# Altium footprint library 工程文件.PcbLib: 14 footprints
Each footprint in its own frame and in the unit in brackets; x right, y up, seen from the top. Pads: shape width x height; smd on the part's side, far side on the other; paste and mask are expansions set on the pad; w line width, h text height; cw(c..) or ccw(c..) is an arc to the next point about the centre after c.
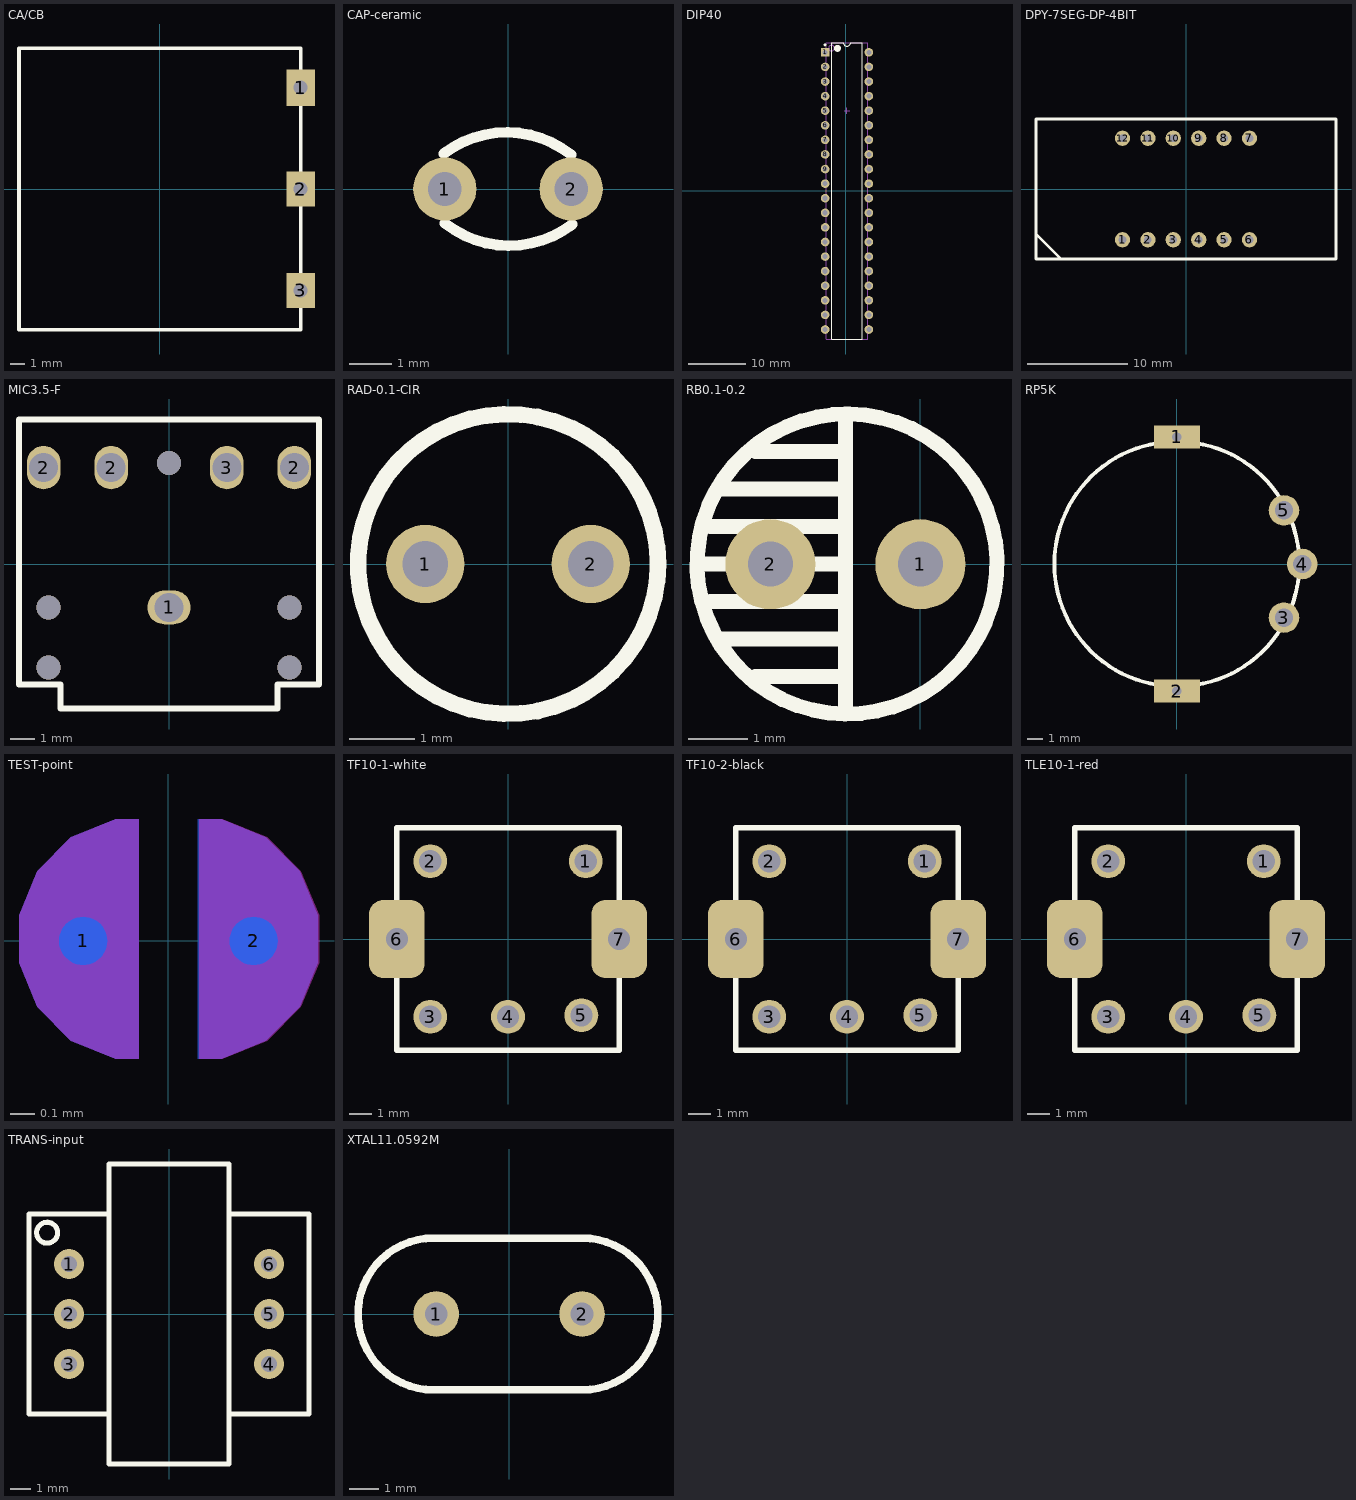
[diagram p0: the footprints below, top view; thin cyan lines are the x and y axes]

## CA/CB [mm]
pads (3):
  rect 2x2.6 hole 1 square: 1(10,7.2)
  rect 2x2.5 hole 1 square: 2(10,0) 3(10,-7.2)
Top Overlay:
  lines w0.254: -10,-10 10,-10 10,10 -10,10 -10,-10

## CAP-ceramic [mm]
pads (2):
  round 1.5 hole 0.8: 1(-1.5,0) 2(1.5,0)
Top Overlay:
  lines w0.254: -1.524,0.838 cw(c-0.029,-1.108) 1.499,0.813 ; -1.499,-0.813 ccw(c0.029,1.108) 1.524,-0.838

## DIP40 [mm]
pads (40):
  rect 1.5x1.5 hole 0.9: 1(-3.556,24.13)
  round 1.5 hole 0.9: 2(-3.556,21.59) 3(-3.556,19.05) 4(-3.556,16.51) 5(-3.556,13.97) 6(-3.556,11.43) 7(-3.556,8.89) 8(-3.556,6.35) 9(-3.556,3.81) 10(-3.556,1.27) 11(-3.556,-1.27) 12(-3.556,-3.81) 13(-3.556,-6.35) 14(-3.556,-8.89) 15(-3.556,-11.43) 16(-3.556,-13.97) 17(-3.556,-16.51) 18(-3.556,-19.05) 19(-3.556,-21.59) 20(-3.556,-24.13) 21(4.064,-24.13) 22(4.064,-21.59) 23(4.064,-19.05) 24(4.064,-16.51) 25(4.064,-13.97) 26(4.064,-11.43) 27(4.064,-8.89) 28(4.064,-6.35) 29(4.064,-3.81) 30(4.064,-1.27) 32(4.064,3.81) 33(4.064,6.35) 34(4.064,8.89) 35(4.064,11.43) 36(4.064,13.97) 37(4.064,16.51) 38(4.064,19.05) 39(4.064,21.59) 40(4.064,24.13)
  round 1.524 hole 0.762: 31(4.064,1.27)
Top Overlay:
  circle w0.6: c-1.396,24.82 r0.3
  circle w0.25: c-3.556,25.43 r0.125
  lines w0.2: -2.396,-25.781 -2.396,25.82 -0.381,25.82 ccw(c0.254,25.82) 0.889,25.82 2.904,25.82 2.904,-25.781 -2.396,-25.781
Mechanical 13:
  circle w0.1: c-2.446,24.87 r0.5
  lines w0.1: -3.346,-25.781 -3.346,25.77 3.854,25.77 3.854,-25.781 -3.346,-25.781
Mechanical 15:
  lines w0.1: -0.246,13.97 0.754,13.97 ; 0.254,13.47 0.254,14.47
3D body: height 5.08, standoff 0, extent -3.346,-25.781 3.854,25.77

## DPY-7SEG-DP-4BIT [mil]
pads (12):
  round 60 hole 30: 1(-250,-200) 2(-150,-200) 3(-50,-200) 4(50,-200) 5(150,-200) 6(250,-200) 7(250,200) 8(150,200) 9(50,200) 10(-50,200) 11(-150,200) 12(-250,200)
Top Overlay:
  lines w10: -590.55,-177.17 -492.13,-275.59 ; -590.55,-275.59 590.55,-275.59 590.55,275.59 -590.55,275.59 -590.55,-275.59

## MIC3.5-F [mm]
pads (5):
  oval 1.8x1.4 hole 1.2: 1(0,-1.8)
  oval 1.4x1.8 hole 1.2: 2(-5.2,4) 2(-2.4,4) 2(5.2,4) 3(2.4,4)
via 5,-1.8 diameter 1 hole 1
via 5,-4.3 diameter 1 hole 1
via -5,-1.8 diameter 1 hole 1
via -5,-4.3 diameter 1 hole 1
via 0,4.191 diameter 1 hole 1
Top Overlay:
  lines w0.254: -6.223,-5 -6.223,6 6.223,6 6.223,-5 4.5,-5 4.5,-6 -4.5,-6 -4.5,-5 -6.223,-5

## RAD-0.1-CIR [mm]
pads (2):
  round 1.2 hole 0.7: 1(-1.27,0) 2(1.27,0)
Top Overlay:
  circle w0.254: c0,0 r2.302

## RB0.1-0.2 [mil]
pads (2):
  round 60 hole 30: 1(0,0) 2(-100,0)
Top Overlay:
  lines w10: -145,0 -55,0 ; -140,-25 -50,-25 ; -140,25 -50,25 ; -135,-50 -50,-50 ; -135,50 -50,50 ; -110,-75 -50,-75 ; -110,75 -50,75 ; -50,-95 -50,100 ; 50,15 ccw(c-48.89,0.17) 50,15

## RP5K [mm]
pads (5):
  rect 3x1.5 hole 0.6 square: 1(0,8.3) 2(0,-8.3)
  round 2 hole 1.2: 3(7,-3.5) 4(8.2,0) 5(7,3.5)
Top Overlay:
  circle w0.254: c0,0 r8

## TEST-point [mm]
pads (2):
  round 0.2 smd far side: 1(-0.356,0) 2(0.356,0)
Bottom Layer:
  region: 0.123,-0.492 0.223,-0.492 0.406,-0.416 0.547,-0.275 0.623,-0.092 0.623,0.107 0.547,0.291 0.406,0.432 0.223,0.508 0.123,0.508
  region: -0.123,-0.492 -0.223,-0.492 -0.406,-0.416 -0.547,-0.275 -0.623,-0.092 -0.623,0.107 -0.547,0.291 -0.406,0.432 -0.223,0.508 -0.123,0.508
Bottom Solder keep-out:
  region: 0.128,-0.492 0.228,-0.492 0.411,-0.416 0.552,-0.275 0.628,-0.091 0.628,0.107 0.552,0.291 0.411,0.432 0.228,0.508 0.128,0.508
  region: -0.123,-0.492 -0.223,-0.492 -0.406,-0.416 -0.547,-0.275 -0.623,-0.092 -0.623,0.107 -0.547,0.291 -0.406,0.432 -0.223,0.508 -0.123,0.508

## TF10-1-white [mm]
pads (7):
  round 1.524 hole 1: 1(3.5,3.5) 2(-3.5,3.5) 3(-3.5,-3.5) 4(0,-3.5) 5(3.302,-3.429)
  rrect50% 2.5x3.5 hole 1 square: 6(-5,0) 7(5,0)
Top Overlay:
  lines w0.254: -5,-5 5,-5 5,5 -5,5 -5,-5

## TF10-2-black [mm]
pads (7):
  round 1.524 hole 1: 1(3.5,3.5) 2(-3.5,3.5) 3(-3.5,-3.5) 4(0,-3.5) 5(3.302,-3.429)
  rrect50% 2.5x3.5 hole 1 square: 6(-5,0) 7(5,0)
Top Overlay:
  lines w0.254: -5,-5 5,-5 5,5 -5,5 -5,-5

## TLE10-1-red [mm]
pads (7):
  round 1.524 hole 1: 1(3.5,3.5) 2(-3.5,3.5) 3(-3.5,-3.5) 4(0,-3.5) 5(3.302,-3.429)
  rrect50% 2.5x3.5 hole 1 square: 6(-5,0) 7(5,0)
Top Overlay:
  lines w0.254: -5,-5 -5,5 5,5 5,-5 -5,-5

## TRANS-input [mm]
pads (6):
  round 1.5 hole 0.8: 1(-5,2.5) 2(-5,0) 3(-5,-2.5) 4(5,-2.5) 5(5,0) 6(5,2.5)
Top Overlay:
  circle w0.254: c-6.096,4.064 r0.524
  lines w0.254: -3,-5 -7,-5 -7,5 -3,5 ; 3,-5 7,-5 7,5 3,5 ; -3,-7.5 3,-7.5 3,7.5 -3,7.5 -3,-7.5

## XTAL11.0592M [mil]
pads (2):
  round 60 hole 30: 1(-96,0) 2(96,0)
Top Overlay:
  lines w10: -100,-100 100,-100 ; -100,100 100,100 ; -99,-100 cw(c-99,0) -99,100 ; 96,-100 ccw(c96,0) 96,100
